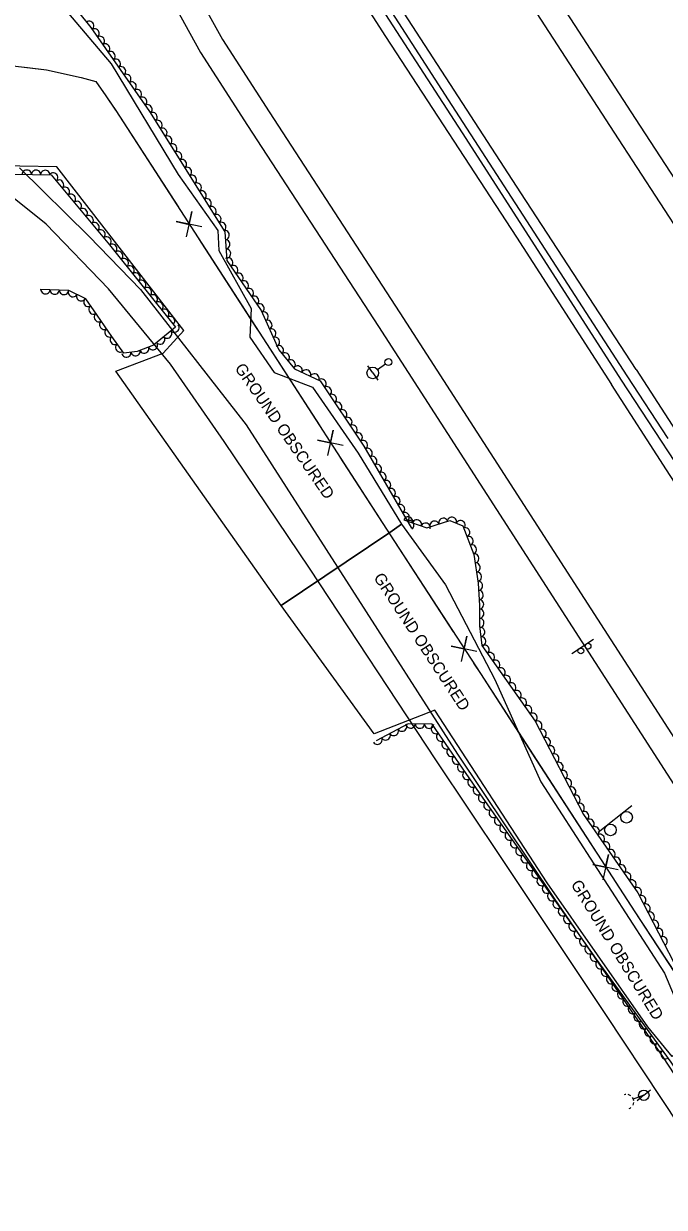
# Model space of a CAD drawing. Extents: x 1746719 to 1766531, y 631721 to 662391.
# Drawn here: x 1760882 to 1761159, y 639416 to 639928 of the extents above; entities that cross this region are included whole.
import ezdxf

# ---------------------------------------------------------------- set-up
doc = ezdxf.new("R2010")
doc.units = 0
for name, color, linetype in [('SURVEY - AERIAL SURVEY - Photo Control - Points - Elevations', 7, 'Continuous'), ('SURVEY - AERIAL SURVEY - Photo Control - Points - Locators', 7, 'Continuous'), ('SURVEY - AERIAL SURVEY - Photo Control - Points - Numbers', 7, 'Continuous'), ('SURVEY - AERIAL SURVEY - Photo Control with Text', 7, 'Continuous'), ('SURVEY - CENTERLINE - Existing Roads - Development', 7, 'Continuous'), ('SURVEY - CENTERLINE - Existing Roads Curve Text', 7, 'Continuous'), ('SURVEY - CONTROL - Grid', 7, 'Continuous')]:
    doc.layers.add(name, color=color, linetype=linetype)

msp = doc.modelspace()

# ---------------------------------------------------------------- linework, layer by layer
at = {"layer": 'SURVEY - AERIAL SURVEY - Photo Control - Points - Elevations'}
for p, q in [((1760885.27, 640071.83), (1760968.31, 639921.13)), ((1760875.81, 640066.21), (1760958.85, 639915.5))]:
    msp.add_line(p, q, dxfattribs=at)
for points in [[(1761196.4, 639810.64), (1761146.73, 639886.96), (1761080.18, 639989.67), (1761013.55, 640093.35), (1760935.82, 640212.96), (1760859, 640331.61), (1760773.89, 640462.5), (1760694.04, 640586.22), (1760626.17, 640690.93), (1760539.47, 640824.63), (1760468.8, 640933.89), (1760453.88, 640957.11)], [(1761187.18, 639804.64), (1761137.51, 639880.97), (1761070.94, 639983.7), (1761004.31, 640087.38), (1760926.59, 640206.97), (1760849.77, 640325.63), (1760764.66, 640456.52), (1760684.8, 640580.25), (1760616.94, 640684.94), (1760530.24, 640818.65), (1760459.56, 640927.93), (1760444.62, 640951.16)], [(1761146.95, 639778.46), (1761097.25, 639854.83), (1761030.61, 639957.68), (1760963.99, 640061.33), (1760886.32, 640180.85), (1760809.51, 640299.5), (1760724.37, 640430.42), (1760644.5, 640554.18), (1760576.67, 640658.83), (1760489.95, 640792.56), (1760419.21, 640901.92), (1760404.24, 640925.21)], [(1760393.74, 640918.4), (1760441.13, 640845.23), (1760507.05, 640743.21), (1760565.58, 640652.81), (1760626.82, 640558.41), (1760688.54, 640463.7), (1760741.79, 640381.9), (1760794.12, 640301.16), (1760851.62, 640212.52), (1760925.86, 640097.46), (1760981.18, 640012.09), (1761038.81, 639922.4), (1761095.32, 639835.55), (1761136.33, 639771.93)], [(1760968.31, 639921.13), (1760988.43, 639889.82), (1761044.96, 639802.94), (1761283.77, 639432.49)], [(1760958.85, 639915.5), (1760979.19, 639883.84), (1761035.73, 639796.96), (1761200.18, 639541.86)], [(1761060.73, 639609.21), (1761005.99, 639692.54), (1760969.05, 639747.28), (1760945.82, 639780.73), (1760919.14, 639813.28), (1760892.23, 639841.3), (1760857.88, 639868.57)], [(1760880.61, 639865.56), (1760910.73, 639835.85), (1760932.93, 639812.98), (1760978.57, 639754.45), (1761069.86, 639612.18)], [(1761146.95, 639778.46), (1761195.22, 639703.73), (1761251.44, 639616.68), (1761313.08, 639522.15), (1761377.89, 639421.23), (1761432.01, 639335.58), (1761475.36, 639265.56), (1761542.97, 639154.5), (1761589.49, 639077.17), (1761635.62, 638998.41), (1761675.75, 638925.66)], [(1761602.12, 639030.42), (1761568.6, 639088.13), (1761526.06, 639158.89), (1761478.26, 639237.73), (1761426.19, 639322.37), (1761373.56, 639405.11), (1761312.03, 639500.83), (1761257.81, 639584.55), (1761207.27, 639662.11), (1761160.18, 639735.07), (1761136.33, 639771.93)], [(1761328.6, 639160.65), (1761319.57, 639195.02), (1761308.24, 639224.98), (1761289.38, 639259.93), (1761263.23, 639301.63), (1761244.81, 639330.91), (1761217.46, 639372.48), (1761182, 639426.94), (1761133.85, 639499.67), (1761089.34, 639566.55), (1761060.73, 639609.21)], [(1761069.86, 639612.18), (1761111.53, 639549.72), (1761158.43, 639481.4), (1761192.53, 639429.29), (1761227.85, 639374.45), (1761262.18, 639322.21), (1761295.15, 639269.44), (1761307.94, 639246.03), (1761324.87, 639210.95), (1761335.11, 639171.62), (1761341.09, 639139.6)]]:
    msp.add_lwpolyline(points, dxfattribs=at)
at = {"layer": 'SURVEY - AERIAL SURVEY - Photo Control - Points - Locators'}
for points in [[(1760893.82, 639941.94), (1760920.2, 639910.59), (1760949.14, 639862.72), (1760966.26, 639838.47), (1760966.7, 639829.9), (1760980.76, 639804.74), (1760980.12, 639792.36), (1760990.64, 639777.16), (1761007.19, 639770.82), (1761026.92, 639742.25), (1761045.65, 639711.53), (1761040.55, 639708), (1760993.64, 639676.38), (1760922.23, 639777.75), (1760942.71, 639785.52), (1760951.61, 639795.25), (1760896.86, 639866.04), (1760880.8, 639866.35), (1760860.56, 639867.28), (1760843.81, 639891.17), (1760821.5, 639912.62), (1760794.19, 639914.28), (1760734.39, 639997.35)], [(1761045.65, 639711.53), (1761064.63, 639685.38), (1761086.04, 639644.36), (1761105.9, 639600.11), (1761159.22, 639517.53), (1761171.71, 639487.58), (1761162.57, 639481.48), (1761152.03, 639494.29), (1761108.56, 639556.54), (1761059.99, 639631.19), (1761033.83, 639620.9), (1760993.64, 639676.38), (1761040.55, 639708), (1761045.65, 639711.53)]]:
    msp.add_lwpolyline(points, dxfattribs=at)
at = {"layer": 'SURVEY - AERIAL SURVEY - Photo Control - Points - Numbers'}
msp.add_line((1761143.02, 639775.73), (1761160.76, 639748.53), dxfattribs=at)
for points in [[(1760398.55, 640924.9), (1760464.19, 640823.64), (1760557.54, 640679.57), (1760643.46, 640547.14), (1760726.42, 640418.31), (1760797.81, 640309.01), (1760889.3, 640167.21), (1760984.42, 640021.34), (1761065.75, 639894.94), (1761143.02, 639775.73)], [(1761140.67, 639773.85), (1761073.58, 639878.26), (1760990.71, 640006.56), (1760880.55, 640175.62), (1760768.9, 640348.2), (1760647.19, 640535.4), (1760552.29, 640681.96), (1760459.27, 640825.92), (1760396.33, 640923.21)], [(1761586.13, 639068.16), (1761558.77, 639113.16), (1761509.79, 639195.15), (1761456.56, 639282.72), (1761407.13, 639360.68), (1761347.65, 639454.84), (1761247.23, 639610.29), (1761178.28, 639716.46), (1761140.67, 639773.85)]]:
    msp.add_lwpolyline(points, dxfattribs=at)
at = {"layer": 'SURVEY - AERIAL SURVEY - Photo Control with Text'}
for points in [[(1760615.3, 640361.22), (1760638.23, 640323.35), (1760659.99, 640289.27), (1760692.62, 640263.25), (1760720.41, 640230.88), (1760752.63, 640201.71), (1760777.47, 640157.41), (1760782.07, 640123.94), (1760807.82, 640080.96), (1760846.27, 640015.51), (1760866.54, 639982.2), (1760911.44, 639926.31), (1760936.78, 639889.91), (1760969.28, 639837.95), (1760970.25, 639825.6), (1760985.06, 639803.91), (1760992.67, 639786.95), (1760999.45, 639778.75), (1761010.48, 639773.5), (1761029.44, 639745.28), (1761049.95, 639709.8)], [(1760861.8, 639863.15), (1760894.35, 639862.58), (1760919.58, 639832.3), (1760947.99, 639796.69), (1760938.59, 639788.88), (1760931.45, 639786.26), (1760925.79, 639785.52), (1760920.58, 639792.69), (1760914.23, 639801.87), (1760909.36, 639808.91), (1760901.93, 639812.61), (1760889.58, 639813.04)], [(1761046.66, 639713.48), (1761056.67, 639709.97), (1761066.49, 639713.1), (1761072.15, 639710.88), (1761076.94, 639698.42), (1761078.75, 639686.07), (1761079.31, 639676.41), (1761079.41, 639667.64), (1761080.38, 639659.16), (1761103.43, 639626.46), (1761124.21, 639586.07), (1761147.72, 639552.14), (1761174.44, 639500.68), (1761189.69, 639478.88), (1761217.85, 639446.3), (1761236.94, 639418.75), (1761247.81, 639403.07)], [(1761210.64, 639405.45), (1761162.11, 639478.94), (1761129.83, 639523.5), (1761080.87, 639593.09), (1761058.89, 639625.14), (1761048.47, 639625.28), (1761034.68, 639617.94)]]:
    msp.add_lwpolyline(points, dxfattribs=at)
for centre, major_axis in [((1760910.86, 639927.03), (1.25, -1.56)), ((1760913.2, 639923.78), (1.14, -1.64)), ((1760915.48, 639920.5), (1.14, -1.64)), ((1760917.77, 639917.22), (1.14, -1.64)), ((1760920.05, 639913.93), (1.14, -1.64)), ((1760922.34, 639910.65), (1.14, -1.64)), ((1760924.62, 639907.37), (1.14, -1.64)), ((1760926.91, 639904.08), (1.14, -1.64)), ((1760929.2, 639900.8), (1.14, -1.64)), ((1760931.48, 639897.52), (1.14, -1.64)), ((1760933.77, 639894.24), (1.14, -1.64)), ((1760936.05, 639890.95), (1.14, -1.64)), ((1760938.22, 639887.6), (1.06, -1.7)), ((1760940.35, 639884.2), (1.06, -1.7)), ((1760942.47, 639880.81), (1.06, -1.7)), ((1760944.59, 639877.42), (1.06, -1.7)), ((1760946.71, 639874.03), (1.06, -1.7)), ((1760948.83, 639870.64), (1.06, -1.7)), ((1760883.8, 639862.77), (2, -0.03)), ((1760950.95, 639867.25), (1.06, -1.7)), ((1760953.07, 639863.86), (1.06, -1.7)), ((1760887.8, 639862.7), (2, -0.03)), ((1760891.8, 639862.63), (2, -0.03)), ((1760895.28, 639861.47), (1.28, -1.54)), ((1760897.84, 639858.39), (1.28, -1.54)), ((1760955.2, 639860.47), (1.06, -1.7)), ((1760900.4, 639855.32), (1.28, -1.54)), ((1760902.96, 639852.25), (1.28, -1.54)), ((1760957.32, 639857.08), (1.06, -1.7)), ((1760959.44, 639853.68), (1.06, -1.7)), ((1760905.52, 639849.17), (1.28, -1.54)), ((1760961.56, 639850.29), (1.06, -1.7)), ((1760908.08, 639846.1), (1.28, -1.54)), ((1760910.64, 639843.03), (1.28, -1.54)), ((1760963.68, 639846.9), (1.06, -1.7)), ((1760965.8, 639843.51), (1.06, -1.7)), ((1760913.2, 639839.96), (1.28, -1.54)), ((1760915.76, 639836.88), (1.28, -1.54)), ((1760967.92, 639840.12), (1.06, -1.7)), ((1760918.32, 639833.81), (1.28, -1.54)), ((1760969.39, 639836.51), (0.16, -1.99)), ((1760969.71, 639832.53), (0.16, -1.99)), ((1760920.85, 639830.71), (1.25, -1.56)), ((1760923.35, 639827.58), (1.25, -1.56)), ((1760970.02, 639828.54), (0.16, -1.99)), ((1760925.84, 639824.46), (1.25, -1.56)), ((1760970.84, 639824.73), (1.13, -1.65)), ((1760928.33, 639821.33), (1.25, -1.56)), ((1760930.83, 639818.2), (1.25, -1.56)), ((1760973.1, 639821.43), (1.13, -1.65)), ((1760975.35, 639818.12), (1.13, -1.65)), ((1760933.32, 639815.07), (1.25, -1.56)), ((1760935.82, 639811.95), (1.25, -1.56)), ((1760977.61, 639814.82), (1.13, -1.65)), ((1760979.86, 639811.52), (1.13, -1.65)), ((1760891.88, 639812.96), (-2, 0.07)), ((1760895.87, 639812.82), (-2, 0.07)), ((1760899.87, 639812.68), (-2, 0.07)), ((1760903.67, 639811.74), (-1.79, 0.89)), ((1760907.25, 639809.96), (-1.79, 0.89)), ((1760910.29, 639807.56), (-1.14, 1.64)), ((1760938.31, 639808.82), (1.25, -1.56)), ((1760982.12, 639808.21), (1.13, -1.65)), ((1760912.57, 639804.27), (-1.14, 1.64)), ((1760940.81, 639805.69), (1.25, -1.56)), ((1760943.3, 639802.57), (1.25, -1.56)), ((1760984.38, 639804.91), (1.13, -1.65)), ((1760986.2, 639801.37), (0.82, -1.82)), ((1760914.85, 639800.98), (-1.14, 1.64)), ((1760917.12, 639797.69), (-1.14, 1.64)), ((1760945.8, 639799.44), (1.25, -1.56)), ((1760987.84, 639797.72), (0.82, -1.82)), ((1760919.4, 639794.4), (-1.14, 1.64)), ((1760944.54, 639793.83), (-1.54, -1.28)), ((1760947.62, 639796.38), (-1.54, -1.28)), ((1760989.47, 639794.07), (0.82, -1.82)), ((1760921.71, 639791.14), (-1.17, 1.62)), ((1760924.06, 639787.9), (-1.17, 1.62)), ((1760934.59, 639787.41), (-1.88, -0.69)), ((1760938.35, 639788.79), (-1.88, -0.69)), ((1760941.47, 639791.27), (-1.54, -1.28)), ((1760991.11, 639790.42), (0.82, -1.82)), ((1760992.79, 639786.8), (1.27, -1.54)), ((1760926.83, 639785.65), (-1.98, -0.26)), ((1760930.8, 639786.18), (-1.98, -0.26)), ((1760995.34, 639783.71), (1.27, -1.54)), ((1760997.89, 639780.63), (1.27, -1.54)), ((1761000.85, 639778.08), (1.81, -0.86)), ((1761004.47, 639776.36), (1.81, -0.86)), ((1761008.08, 639774.64), (1.81, -0.86)), ((1761011.23, 639772.38), (1.12, -1.66)), ((1761013.46, 639769.06), (1.12, -1.66)), ((1761015.69, 639765.74), (1.12, -1.66)), ((1761017.92, 639762.42), (1.12, -1.66)), ((1761020.15, 639759.1), (1.12, -1.66)), ((1761022.38, 639755.78), (1.12, -1.66)), ((1761024.61, 639752.46), (1.12, -1.66)), ((1761026.84, 639749.14), (1.12, -1.66)), ((1761029.07, 639745.82), (1.12, -1.66)), ((1761031.11, 639742.38), (1, -1.73)), ((1761033.11, 639738.92), (1, -1.73)), ((1761035.12, 639735.46), (1, -1.73)), ((1761037.12, 639732), (1, -1.73)), ((1761039.12, 639728.53), (1, -1.73)), ((1761041.12, 639725.07), (1, -1.73)), ((1761043.12, 639721.61), (1, -1.73)), ((1761045.13, 639718.14), (1, -1.73)), ((1761047.13, 639714.68), (1, -1.73)), ((1761048.55, 639712.82), (1.89, -0.66)), ((1761049.13, 639711.22), (1, -1.73)), ((1761052.32, 639711.5), (1.89, -0.66)), ((1761056.1, 639710.17), (1.89, -0.66)), ((1761059.9, 639711), (1.91, 0.61)), ((1761063.72, 639712.22), (1.91, 0.61)), ((1761067.5, 639712.71), (1.86, -0.73)), ((1761071.22, 639711.24), (1.86, -0.73)), ((1761073.23, 639708.07), (0.72, -1.87)), ((1761074.67, 639704.34), (0.72, -1.87)), ((1761076.1, 639700.61), (0.72, -1.87)), ((1761077.18, 639696.78), (0.29, -1.98)), ((1761077.76, 639692.82), (0.29, -1.98)), ((1761078.34, 639688.86), (0.29, -1.98)), ((1761078.81, 639684.9), (0.12, -2)), ((1761079.05, 639680.9), (0.12, -2)), ((1761079.28, 639676.91), (0.12, -2)), ((1761079.35, 639672.91), (0.02, -2)), ((1761079.4, 639668.91), (0.02, -2)), ((1761079.72, 639664.93), (0.23, -1.99)), ((1761080.17, 639660.95), (0.23, -1.99)), ((1761081.64, 639657.36), (1.15, -1.63)), ((1761083.94, 639654.1), (1.15, -1.63)), ((1761086.25, 639650.83), (1.15, -1.63)), ((1761088.55, 639647.56), (1.15, -1.63)), ((1761090.86, 639644.29), (1.15, -1.63)), ((1761093.16, 639641.02), (1.15, -1.63)), ((1761095.47, 639637.75), (1.15, -1.63)), ((1761097.77, 639634.48), (1.15, -1.63)), ((1761100.08, 639631.21), (1.15, -1.63)), ((1761102.38, 639627.94), (1.15, -1.63)), ((1761045.92, 639623.92), (-1.77, -0.94)), ((1761049.58, 639625.26), (-2, 0.03)), ((1761053.58, 639625.21), (-2, 0.03)), ((1761057.58, 639625.16), (-2, 0.03)), ((1761060.41, 639622.92), (-1.13, 1.65)), ((1761104.43, 639624.52), (0.91, -1.78)), ((1761035.33, 639618.29), (-1.77, -0.94)), ((1761038.86, 639620.17), (-1.77, -0.94)), ((1761042.39, 639622.05), (-1.77, -0.94)), ((1761062.67, 639619.62), (-1.13, 1.65)), ((1761106.26, 639620.96), (0.91, -1.78)), ((1761108.09, 639617.4), (0.91, -1.78)), ((1761064.94, 639616.32), (-1.13, 1.65)), ((1761067.2, 639613.02), (-1.13, 1.65)), ((1761109.92, 639613.84), (0.91, -1.78)), ((1761069.46, 639609.72), (-1.13, 1.65)), ((1761111.75, 639610.29), (0.91, -1.78)), ((1761113.58, 639606.73), (0.91, -1.78)), ((1761071.72, 639606.42), (-1.13, 1.65)), ((1761073.98, 639603.13), (-1.13, 1.65)), ((1761115.4, 639603.17), (0.91, -1.78)), ((1761076.25, 639599.83), (-1.13, 1.65)), ((1761117.23, 639599.62), (0.91, -1.78)), ((1761078.51, 639596.53), (-1.13, 1.65)), ((1761080.77, 639593.23), (-1.13, 1.65)), ((1761119.06, 639596.06), (0.91, -1.78)), ((1761120.89, 639592.5), (0.91, -1.78)), ((1761083.07, 639589.96), (-1.15, 1.64)), ((1761122.72, 639588.95), (0.91, -1.78)), ((1761085.37, 639586.69), (-1.15, 1.64)), ((1761087.68, 639583.41), (-1.15, 1.64)), ((1761124.64, 639585.44), (1.14, -1.64)), ((1761126.92, 639582.15), (1.14, -1.64)), ((1761089.98, 639580.14), (-1.15, 1.64)), ((1761092.28, 639576.87), (-1.15, 1.64)), ((1761129.2, 639578.86), (1.14, -1.64)), ((1761094.58, 639573.6), (-1.15, 1.64)), ((1761131.47, 639575.58), (1.14, -1.64)), ((1761133.75, 639572.29), (1.14, -1.64)), ((1761096.88, 639570.33), (-1.15, 1.64)), ((1761099.18, 639567.06), (-1.15, 1.64)), ((1761136.03, 639569), (1.14, -1.64)), ((1761138.31, 639565.71), (1.14, -1.64)), ((1761101.49, 639563.79), (-1.15, 1.64)), ((1761140.59, 639562.43), (1.14, -1.64)), ((1761103.79, 639560.52), (-1.15, 1.64)), ((1761106.09, 639557.24), (-1.15, 1.64)), ((1761142.86, 639559.14), (1.14, -1.64)), ((1761145.14, 639555.85), (1.14, -1.64)), ((1761108.39, 639553.97), (-1.15, 1.64)), ((1761147.42, 639552.56), (1.14, -1.64)), ((1761110.69, 639550.7), (-1.15, 1.64)), ((1761113, 639547.43), (-1.15, 1.64)), ((1761149.32, 639549.05), (0.92, -1.77)), ((1761151.17, 639545.5), (0.92, -1.77)), ((1761115.3, 639544.16), (-1.15, 1.64)), ((1761117.6, 639540.89), (-1.15, 1.64)), ((1761153.01, 639541.95), (0.92, -1.77)), ((1761119.9, 639537.62), (-1.15, 1.64)), ((1761154.85, 639538.4), (0.92, -1.77)), ((1761122.2, 639534.34), (-1.15, 1.64)), ((1761124.5, 639531.07), (-1.15, 1.64)), ((1761156.7, 639534.85), (0.92, -1.77)), ((1761158.54, 639531.3), (0.92, -1.77)), ((1761126.81, 639527.8), (-1.15, 1.64)), ((1761129.11, 639524.53), (-1.15, 1.64)), ((1761131.44, 639521.28), (-1.17, 1.62)), ((1761133.79, 639518.04), (-1.17, 1.62)), ((1761136.13, 639514.8), (-1.17, 1.62)), ((1761138.48, 639511.56), (-1.17, 1.62)), ((1761140.83, 639508.32), (-1.17, 1.62)), ((1761143.17, 639505.08), (-1.17, 1.62)), ((1761145.52, 639501.84), (-1.17, 1.62)), ((1761147.86, 639498.6), (-1.17, 1.62)), ((1761150.21, 639495.36), (-1.17, 1.62)), ((1761152.56, 639492.12), (-1.17, 1.62)), ((1761154.9, 639488.89), (-1.17, 1.62)), ((1761157.25, 639485.65), (-1.17, 1.62)), ((1761159.6, 639482.41), (-1.17, 1.62))]:
    msp.add_ellipse(centre, major_axis=major_axis, ratio=0.940188, start_param=0, end_param=3.141593, dxfattribs=at)
at = {"layer": 'SURVEY - CENTERLINE - Existing Roads - Development'}
for p, q in [((1761033.24, 639776.91), (1761031.1, 639779.99)), ((1761038.78, 639780.75), (1761035.29, 639778.33)), ((1761033.24, 639776.91), (1761035.37, 639773.82)), ((1761150.33, 639464.69), (1761153.2, 639467.11)), ((1761150.33, 639464.69), (1761145.79, 639463.01)), ((1761146.45, 639463.25), (1761145.79, 639463.01)), ((1761150.33, 639464.69), (1761147.47, 639462.27))]:
    msp.add_line(p, q, dxfattribs=at)
for centre, radius in [((1761040.02, 639781.6), 1.5), ((1761033.24, 639776.91), 2.5), ((1761150.33, 639464.69), 2.25)]:
    msp.add_circle(centre, radius, dxfattribs=at)
for start_param, end_param in [(2.883049, 3.125465), (2.156577, 2.588895), (1.352995, 1.815775), (0.730907, 1.085951), (0, 0.255182)]:
    msp.add_ellipse((1761142.9, 639461.9), major_axis=(1.09, -2.93), ratio=0.997931, start_param=start_param, end_param=end_param, dxfattribs=at)
at = {"layer": 'SURVEY - CENTERLINE - Existing Roads Curve Text'}
for points in [[(1760817.19, 639915.7), (1760829.41, 639915.49), (1760892.31, 639907.9), (1760907.36, 639904.68), (1760913.63, 639902.87), (1760917.97, 639896.71), (1760922.29, 639890.35), (1760984.17, 639794.48), (1761040.76, 639706.94)], [(1760882.9, 639909.04), (1760892.31, 639907.9), (1760907.36, 639904.68), (1760913.63, 639902.87), (1760917.97, 639896.71), (1760922.17, 639890.53)], [(1760922.17, 639890.53), (1760922.29, 639890.35), (1760949.29, 639848.52)], [(1760959.4, 639840.05), (1760948.39, 639842.35), (1760953.92, 639841.16), (1760955.11, 639846.69), (1760952.68, 639835.71)], [(1760958.02, 639834.99), (1760983.18, 639796.01)], [(1760983.18, 639796.01), (1760984.17, 639794.48), (1761010.33, 639754.02)], [(1761020.44, 639745.55), (1761009.43, 639747.84), (1761014.97, 639746.66), (1761016.15, 639752.19), (1761013.72, 639741.21)], [(1761019.07, 639740.5), (1761040.76, 639706.94)], [(1761040.76, 639706.94), (1761079.73, 639646.97), (1761146.4, 639544.01), (1761195.13, 639469.86), (1761267.22, 639357.22), (1761326.8, 639262.19), (1761361.22, 639206.51)], [(1761040.76, 639706.94), (1761068, 639665.01)], [(1761078.14, 639656.57), (1761067.13, 639658.84), (1761072.66, 639657.66), (1761073.83, 639663.2), (1761071.43, 639652.21)], [(1761076.78, 639651.51), (1761079.73, 639646.97), (1761102, 639612.57)], [(1761102, 639612.57), (1761129.18, 639570.6)], [(1761139.3, 639562.14), (1761128.29, 639564.42), (1761133.82, 639563.24), (1761135.01, 639568.77), (1761132.58, 639557.79)], [(1761137.93, 639557.08), (1761146.4, 639544.01), (1761163.32, 639518.25)]]:
    msp.add_lwpolyline(points, dxfattribs=at)
at = {"layer": 'SURVEY - CONTROL - Grid'}
for p, q in [((1761119.25, 639655.69), (1761128.6, 639661.86)), ((1761145.08, 639589.8), (1761130.57, 639578.34)), ((1761142.85, 639584.85), (1761142.85, 639584.85)), ((1761142.85, 639584.85), (1761142.85, 639584.85)), ((1761135.9, 639579.36), (1761135.9, 639579.36)), ((1761135.9, 639579.36), (1761135.9, 639579.36))]:
    msp.add_line(p, q, dxfattribs=at)
for centre, radius in [((1761126.24, 639658.83), 1.25), ((1761123.11, 639656.77), 1.25), ((1761142.86, 639584.87), 2.5), ((1761142.86, 639584.87), 2.5), ((1761135.9, 639579.38), 2.5), ((1761135.9, 639579.38), 2.5)]:
    msp.add_circle(centre, radius, dxfattribs=at)

# ---------------------------------------------------------------- texts
at = {"layer": 'SURVEY - AERIAL SURVEY - Photo Control - Points - Locators'}
for rotation, p in [(304.6744, (1760973.42, 639778.96)), (303.1823, (1761033.41, 639688.47)), (301.4788, (1761118.62, 639555.9))]:
    msp.add_text('GROUND OBSCURED', height=5, rotation=rotation, dxfattribs=at).set_placement(p)

doc.saveas('drawing.dxf')
